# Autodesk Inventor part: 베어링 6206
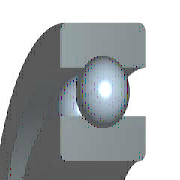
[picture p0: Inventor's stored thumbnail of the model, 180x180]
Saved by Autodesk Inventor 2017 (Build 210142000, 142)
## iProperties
Created: 2009-02
Part Number: 베어링 6206
Material: 강철, 연강
Document SubType Name: Modeling
Standard: KS B 2023
Designer: mdu
Standards Organization: KS
Language: ko-KR
Size Designation: 6206 - 30 x 62 x 16
Categories: <MemberInstance><Categories><Category DisplayName="샤프트 부품" InternalName="7f7aeb1f-a693-4053-b835-cee3144e0d98" Mnemonic="SHFT"><Category DisplayName="베어링" Inter
Density: 1 g/cm^3
Appearance: 노란색
IsCustomPart: 0
Author: mdu
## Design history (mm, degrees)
sketch "스케치" dims "d0" = 8.32 (= -0.26 x WD + 0.26 x BD)
  geometry: L1 (3.84, 23)-(12.16, 23); L2 (8, 23)-(8, 18.84); L3 (8, 23)-(8, 27.16); L4 (4.909, 20.216)-(0, 20.216); L5 (0, 15)-(16, 15); L6 (4.909, 25.784)-(0, 25.784); L7 (0, 31)-(16, 31); L8 (16, 15)-(16, 20.216); L9 (11.091, 20.216)-(16, 20.216); L10 (11.091, 25.784)-(16, 25.784); L11 (16, 31)-(16, 25.784); L12 (-1.4, 0)-(8.4, 0) reference; L13 (0, -0.3)-(0, 5.3) reference
  constraints: 22 end point, 4 point on line, 2 collinear, 2 perpendicular, 2 symmetric about line, 1 midpoint, 1 parallel, 14 other
  dimensions: "d9" = 30 diameter of L5 L12 (= WD); "d11" = 62 diameter of L7 L12 (= BD); "d12" = 16 distance between parallel lines of L8 L13 (= KB); "d13" = 40.432 diameter of L9 L12 (= 0.326 x BD + 0.674 x WD)
revolve "본체" stored, may be unused: angle "d6" = 90 deg
revolve "볼" stored, may be unused: angle "d7" = 90 deg
pattern_circular "IDS_ARRAYBALL[SIMPL:T]" dims angle "d3" = 360 deg
body "Solid1"
fillet "모깎기1" dims "d1" = 1 (= KRS)
other parameters: "WD" = 30 [user parameter; used in 5 equation terms], "BD" = 62 [user parameter; used in 5 equation terms], "KB" = 16 [user parameter; used in 1 equation term], "KRS" = 1 [user parameter; used in 1 equation term], "d4" = 0, "d5" = 0, "d8" = 0, "d14" = 0, "d15" = 0, "BBA" = 0 [user parameter], "BC0" = 1.12e+07 [user parameter], "BC" = 1.95e+07 [user parameter], "BR" = 31 (= 0.5 x BD) [user parameter], "WR" = 15 (= 0.5 x WD) [user parameter]
